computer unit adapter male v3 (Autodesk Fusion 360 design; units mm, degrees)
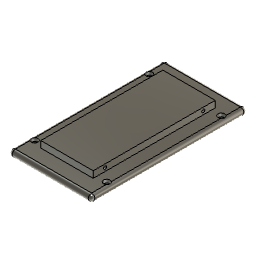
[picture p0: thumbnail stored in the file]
sketch "草图1" plane through (0, 0, 0) normal (0, 0, 1) x axis (1, 0, 0)
  line L1 (25.25, 0) -> (-25.25, 0)
  line L2 (20.25, -41.5) -> (20.25, 41.5)
  line L3 (-20.25, -41.5) -> (20.25, -41.5)
  line L4 (-20.25, 41.5) -> (-20.25, -41.5)
  line L5 (20.25, 41.5) -> (-20.25, 41.5)
  line L6 (25.25, -47.5) -> (-25.25, -47.5)
  line L7 (-25.25, 47.5) -> (25.25, 47.5)
  line L8 (-25.25, -47.5) -> (-25.25, 47.5)
  line L9 (25.25, 47.5) -> (25.25, -47.5)
  line L10 (0, -47.5) -> (0, 47.5)
  line L11 (-16, -37.25) -> (16, -37.25)
  line L12 (-16, 37.25) -> (-16, -37.25)
  line L13 (16, 37.25) -> (-16, 37.25)
  line L14 (16, -37.25) -> (16, 37.25)
  circle C1 centre (22, 35) radius 0.975
  circle C2 centre (-22, 35) radius 0.975
  circle C3 centre (-22, -35) radius 0.975
  circle C4 centre (22, -35) radius 0.975
  circle C5 centre (-22, 35) radius 1.975
  circle C6 centre (22, 35) radius 1.975
  circle C7 centre (-22, -35) radius 1.975
  circle C8 centre (22, -35) radius 1.975
  point P3 (-25.25, 0)
  point P4 (25.25, 0)
  point P6 (0, 47.5)
  point P9 (0, -47.5)
  point P19 (0, 0)
  point P10 (0, 0)
  point P8 (22, 35)
  point P11 (-22, 35)
  point P7 (22, -35)
  point P5 (25.25, 47.5)
  point P18 (25.25, -47.5)
  point P2 (-25.25, 47.5)
  point P12 (20.25, -41.5)
  point P13 (20.25, 41.5)
  point P15 (-20.25, 41.5)
  midpoint P3 L8
  midpoint P4 L9
  midpoint P6 L7
  midpoint P9 L6
  symmetric C1 C2 L10
  symmetric C1 L1 C4
  symmetric L1 C2 C3
  perpendicular L6 L8
  perpendicular L2 L5
  perpendicular L4 L5
  perpendicular L3 L4
  perpendicular L6 L9
  horizontal L7
  midpoint L1 P19
  coincident P10 P19
  dimension "d1" diameter C1 = 1.95
  dimension "d2" distance P8 P11 = 44
  dimension "d3" distance P7 P8 = 70
  dimension "d4" distance P5 P18 = 95
  dimension "d5" distance P2 P5 = 50.5
  dimension "d6" distance P12 P13 = 83
  dimension "d7" distance P13 P15 = 40.5
  dimension "d8" distance L2 L9 = 5
  dimension "d9" distance L5 L7 = 6
  dimension "d10" = 1
  dimension "d11" = 1
  dimension "d12" = 1
  dimension "d13" = 1
  dimension "d24" = 4.25
extrude "拉伸1" new body sketch "草图1" profile of L2 L3 L4 L5 L6 L7 L8 L9 C5 C6 C7 C8 L12 L14 L13 L11 along normal blind 4
extrude "拉伸2" add sketch "草图1" profile of L12 L14 L13 L11 along normal blind 8
extrude "拉伸3" add sketch "草图1" profile of C1 C2 C3 L2 L4 C4 C5 C6 C7 C8 along normal blind 2
fillet "圆角1" radius 2
fillet "圆角2" radius 2
sketch "草图2" plane through (16, 0, 0) normal (1, 0, 0) x axis (0, 1, 0)
  line L1 (34.0845, 4) -> (-34.0845, 4)
  line L2 (34.0845, 8) -> (34.0845, 4)
  line L3 (-34.0845, 8) -> (34.0845, 8)
  line L4 (-34.0845, 4) -> (-34.0845, 8)
  line L5 (0, 4) -> (0, 8)
  line L6 (30, 6) -> (0, 6)
  line L7 (37.25, 8) -> (37.25, 4)
  line L8 (-37.25, 8) -> (37.25, 8)
  line L9 (-37.25, 4) -> (-37.25, 8)
  line L10 (37.25, 4) -> (-37.25, 4)
  circle C1 centre (30, 6) radius 0.95
  circle C2 centre (-30, 6) radius 0.95
  point P6 (0, 8)
  point P7 (0, 4)
  point P8 (0, 6)
  point P9 (30, 6)
  point P10 (30, 6)
  point P11 (-30, 6)
  midpoint L3 P6
  midpoint L1 P7
  midpoint L5 P8
  perpendicular L5 L6
  coincident P9 P10
  symmetric L5 C1 C2
  dimension "d25" distance P10 P11 = 60
  dimension "d26" diameter C1 = 1.9
extrude "拉伸4" cut sketch "草图2" profile of C1 C2 against normal blind 40.5
fillet "圆角3" radius 2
